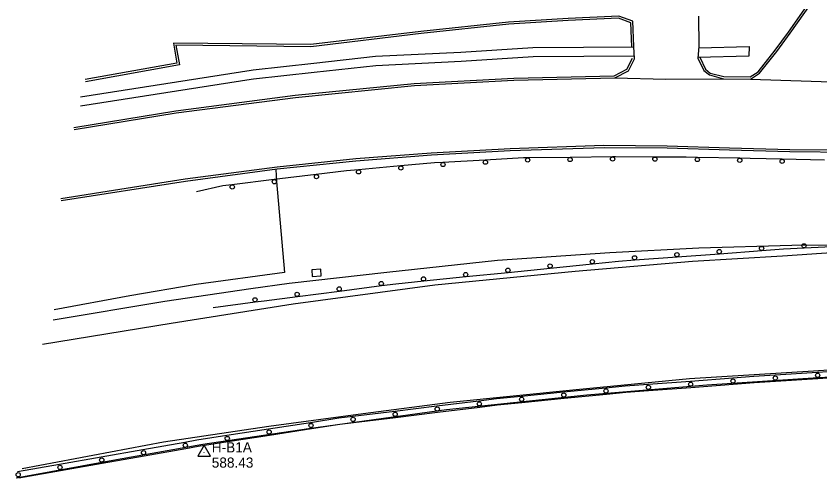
# Model space of a CAD drawing. Extents: x 2402803 to 2427059, y 6985292 to 6997652.
# Drawn here: x 2403515.4 to 2403894.2, y 6991813.9 to 6992031.6 of the extents above; entities that cross this region are included whole.
import ezdxf

# ---------------------------------------------------------------- set-up
doc = ezdxf.new("R2010")
doc.units = 0
for name, color, linetype in [('p_control ground ctrl', 7, 'Continuous'), ('p_drainage riprap', 7, 'Continuous'), ('p_dtm sidewalk', 7, 'Continuous'), ('p_road - paved curb', 7, 'Continuous'), ('p_road bridge end', 7, 'Continuous'), ('p_road conc barrier', 7, 'Continuous'), ('p_road guard rails', 7, 'Continuous'), ('V7 LEVEL 31', 7, 'Continuous')]:
    doc.layers.add(name, color=color, linetype=linetype)

msp = doc.modelspace()

# ---------------------------------------------------------------- linework, layer by layer
at = {"layer": 'p_control ground ctrl'}
for p, q in [((2403604.07, 6991829.43), (2403601.07, 6991824.23)), ((2403607.07, 6991824.23), (2403604.07, 6991829.43)), ((2403604.07, 6991825.95), (2403604.07, 6991825.99)), ((2403601.07, 6991824.23), (2403607.07, 6991824.23))]:
    msp.add_line(p, q, dxfattribs=at)
at = {"layer": 'p_drainage riprap'}
for points in [[(2403637.78, 6991959.32), (2403638.11, 6991953.54), (2403641.89, 6991910.76), (2403600.24, 6991905.07), (2403569.01, 6991899.69), (2403533.3, 6991893.12)], [(2403532.95, 6991888.46), (2403585.58, 6991897.26), (2403626.03, 6991903.26), (2403644.18, 6991905.72), (2403690.09, 6991910.93), (2403742.27, 6991916.53), (2403795.17, 6991920.18), (2403837.2, 6991922.33), (2403880.97, 6991923.55), (2403939.46, 6991923.79)]]:
    msp.add_lwpolyline(points, dxfattribs=at)
at = {"layer": 'p_dtm sidewalk'}
for points in [[(2403806.67, 6992016.94), (2403758.91, 6992016.61), (2403725.03, 6992014.37), (2403684.87, 6992012.47), (2403655.8, 6992009.27), (2403627.13, 6992006.13), (2403626.15, 6992005.91), (2403545.73, 6991993.37)], [(2403837.19, 6992016.66), (2403860.92, 6992017.16), (2403860.8, 6992012.64), (2403836.76, 6992012.09)], [(2403806.79, 6992012.66), (2403759.03, 6992012.33), (2403725.15, 6992010.09), (2403684.99, 6992008.19), (2403655.92, 6992004.99), (2403627.25, 6992001.85), (2403626.27, 6992001.63), (2403545.85, 6991989.09)]]:
    msp.add_lwpolyline(points, dxfattribs=at)
at = {"layer": 'p_road - paved curb'}
for points in [[(2403873.14, 6992015.43), (2403879.35, 6992024.04), (2403892.29, 6992042.47), (2403893.33, 6992046.18)], [(2403873.95, 6992014.85), (2403880.16, 6992023.46), (2403893.21, 6992042.04), (2403894.29, 6992045.91)], [(2403806.6, 6992017.25), (2403806.09, 6992029.16), (2403799.41, 6992031.54), (2403775.54, 6992030.46), (2403747.49, 6992028.7), (2403706.23, 6992024.32), (2403654.28, 6992018.13), (2403589.53, 6992018.84), (2403591.2, 6992009.33), (2403548.02, 6992001.63)], [(2403805.6, 6992017.21), (2403805.12, 6992028.44), (2403799.26, 6992030.53), (2403775.59, 6992029.46), (2403747.57, 6992027.7), (2403706.34, 6992023.33), (2403654.33, 6992017.13), (2403590.72, 6992017.83), (2403592.36, 6992008.52), (2403548.2, 6992000.65)], [(2403837.08, 6992031.56), (2403837.24, 6992017.22), (2403836.73, 6992011.71)], [(2403806.84, 6992011.34), (2403806.6, 6992017.25)], [(2403836.73, 6992011.71), (2403839.47, 6992005.94), (2403842.12, 6992003.81), (2403848.78, 6992002.07), (2403861.58, 6992001.89), (2403865.79, 6992004.6), (2403873.95, 6992014.85)], [(2403837.63, 6992012.14), (2403840.28, 6992006.58), (2403842.58, 6992004.72), (2403848.92, 6992003.07), (2403861.29, 6992002.89), (2403865.11, 6992005.35), (2403873.17, 6992015.47)], [(2403542.69, 6991979.06), (2403590.72, 6991986.9), (2403646.97, 6991994.25), (2403703.09, 6991999.87), (2403749.98, 6992002.37), (2403797.34, 6992003.38), (2403803.27, 6992006.5), (2403805.95, 6992011.79)], [(2403542.85, 6991978.07), (2403590.87, 6991985.91), (2403647.08, 6991993.26), (2403703.17, 6991998.87), (2403750.02, 6992001.37), (2403797.6, 6992002.39), (2403804.02, 6992005.76), (2403806.84, 6992011.34)], [(2403797.57, 6992002.5), (2403821.69, 6992001.76), (2403848.78, 6992002.07)], [(2403861.56, 6992001.89), (2403904.44, 6992000.5)], [(2403936.44, 6991968.29), (2403908.86, 6991968.31), (2403880, 6991968.6), (2403851.7, 6991969.36), (2403822.22, 6991970.3), (2403792.48, 6991970.5), (2403748.26, 6991969.01), (2403711.1, 6991966.96), (2403675.52, 6991964.25), (2403638.41, 6991960.41), (2403595.15, 6991954.64), (2403536.57, 6991945.44)], [(2403936.44, 6991967.29), (2403908.85, 6991967.31), (2403879.98, 6991967.6), (2403851.67, 6991968.36), (2403822.2, 6991969.3), (2403792.49, 6991969.5), (2403748.3, 6991968.01), (2403711.17, 6991965.96), (2403675.61, 6991963.25), (2403638.53, 6991959.42), (2403595.29, 6991953.65), (2403536.73, 6991944.45)], [(2403527.89, 6991876.98), (2403588.45, 6991886.88), (2403645.93, 6991895.97), (2403712.77, 6991904.89), (2403778.83, 6991911.37), (2403834.22, 6991916.11), (2403876.59, 6991918.51), (2403927.12, 6991921.97), (2403942.02, 6991922.78)], [(2403939.09, 6991867.4), (2403891.26, 6991864.17), (2403832.8, 6991860.58), (2403779.29, 6991855.47), (2403719.94, 6991849.45), (2403678.99, 6991844.06), (2403634.61, 6991838.18), (2403584.87, 6991830.81), (2403518.35, 6991818.19)], [(2403515.51, 6991814.01), (2403562.7, 6991822.61), (2403603.5, 6991829.83), (2403653.28, 6991837.15), (2403718.31, 6991846.1), (2403784.34, 6991853.15), (2403840.98, 6991857.79), (2403893.48, 6991861.21), (2403940.14, 6991863.6)]]:
    msp.add_lwpolyline(points, dxfattribs=at)
at = {"layer": 'p_road bridge end'}
msp.add_lwpolyline([(2403654.95, 6991908.81), (2403659.19, 6991909.13), (2403658.96, 6991912.28), (2403654.72, 6991911.96)], close=True, dxfattribs=at)
at = {"layer": 'p_road conc barrier'}
for p, q in [((2403873.13, 6991862.49), (2403893.08, 6991863.81)), ((2403813.28, 6991858.12), (2403833.22, 6991859.6)), ((2403833.22, 6991859.6), (2403853.16, 6991861.08)), ((2403873.33, 6991859.49), (2403893.28, 6991860.82)), ((2403773.41, 6991854.46), (2403793.3, 6991856.42)), ((2403813.51, 6991855.13), (2403833.44, 6991856.61)), ((2403833.44, 6991856.61), (2403853.38, 6991858.09)), ((2403753.51, 6991852.5), (2403773.41, 6991854.46)), ((2403753.81, 6991849.51), (2403773.7, 6991851.47)), ((2403773.7, 6991851.47), (2403793.59, 6991853.43)), ((2403693.88, 6991845.44), (2403713.73, 6991847.88)), ((2403713.73, 6991847.88), (2403733.57, 6991850.33)), ((2403714.09, 6991844.91), (2403733.94, 6991847.35)), ((2403674.04, 6991842.99), (2403693.88, 6991845.44)), ((2403694.25, 6991842.46), (2403714.09, 6991844.91)), ((2403634.44, 6991837.06), (2403654.18, 6991840.12)), ((2403674.41, 6991840.01), (2403694.25, 6991842.46)), ((2403614.71, 6991834), (2403634.44, 6991837.06)), ((2403634.9, 6991834.09), (2403654.64, 6991837.15)), ((2403615.17, 6991831.03), (2403634.9, 6991834.09)), ((2403575.23, 6991827.33), (2403594.92, 6991830.81)), ((2403555.54, 6991823.85), (2403575.23, 6991827.33)), ((2403575.76, 6991824.37), (2403595.45, 6991827.85)), ((2403535.85, 6991820.37), (2403555.54, 6991823.85)), ((2403536.37, 6991817.41), (2403556.06, 6991820.89)), ((2403556.06, 6991820.89), (2403575.76, 6991824.37)), ((2403516.16, 6991816.89), (2403535.85, 6991820.37)), ((2403516.68, 6991813.93), (2403536.37, 6991817.41))]:
    msp.add_line(p, q, dxfattribs=at)
for points in [[(2403853.16, 6991861.08), (2403863.04, 6991861.82), (2403873.13, 6991862.49)], [(2403893.08, 6991863.81), (2403902.86, 6991864.46), (2403913.12, 6991864.89)], [(2403853.38, 6991858.09), (2403863.25, 6991858.82), (2403873.33, 6991859.49)], [(2403893.28, 6991860.82), (2403903.03, 6991861.46), (2403913.25, 6991861.89)], [(2403793.3, 6991856.42), (2403802.53, 6991857.32), (2403813.28, 6991858.12)], [(2403793.59, 6991853.43), (2403802.79, 6991854.34), (2403813.51, 6991855.13)], [(2403733.57, 6991850.33), (2403741.79, 6991851.34), (2403753.51, 6991852.5)], [(2403733.94, 6991847.35), (2403742.12, 6991848.36), (2403753.81, 6991849.51)], [(2403654.18, 6991840.12), (2403667.58, 6991842.2), (2403674.04, 6991842.99)], [(2403654.64, 6991837.15), (2403668, 6991839.22), (2403674.41, 6991840.01)], [(2403594.92, 6991830.81), (2403600.67, 6991831.82), (2403614.71, 6991834)], [(2403595.45, 6991827.85), (2403601.16, 6991828.86), (2403615.17, 6991831.03)]]:
    msp.add_lwpolyline(points, dxfattribs=at)
for centre in [(2403893.18, 6991862.31), (2403833.33, 6991858.11), (2403853.27, 6991859.59), (2403873.23, 6991860.99), (2403793.44, 6991854.92), (2403813.4, 6991856.63), (2403753.66, 6991851), (2403773.55, 6991852.96), (2403713.91, 6991846.39), (2403733.75, 6991848.84), (2403694.07, 6991843.95), (2403674.22, 6991841.5), (2403634.67, 6991835.58), (2403654.41, 6991838.64), (2403614.94, 6991832.52), (2403595.18, 6991829.33), (2403575.49, 6991825.85), (2403555.8, 6991822.37), (2403536.11, 6991818.89), (2403516.42, 6991815.41)]:
    msp.add_circle(centre, 1, dxfattribs=at)
at = {"layer": 'p_road guard rails'}
for p, q in [((2403776.5, 6991964.97), (2403756.51, 6991964.73)), ((2403796.5, 6991965.21), (2403776.5, 6991964.97)), ((2403856.48, 6991964.58), (2403836.49, 6991964.97)), ((2403696.65, 6991960.95), (2403676.73, 6991959.15)), ((2403736.54, 6991963.72), (2403716.57, 6991962.62)), ((2403896.45, 6991963.61), (2403876.47, 6991964.11)), ((2403637.01, 6991954.48), (2403617.15, 6991952.05)), ((2403656.86, 6991956.9), (2403637.01, 6991954.48)), ((2403886.76, 6991922.3), (2403906.7, 6991923.32)), ((2403826.93, 6991918.12), (2403846.87, 6991919.59)), ((2403846.87, 6991919.59), (2403866.82, 6991921.06)), ((2403806.98, 6991916.65), (2403826.93, 6991918.12)), ((2403747.29, 6991910.79), (2403767.18, 6991912.81)), ((2403767.18, 6991912.81), (2403787.07, 6991914.84)), ((2403707.52, 6991906.75), (2403727.41, 6991908.77)), ((2403727.41, 6991908.77), (2403747.29, 6991910.79)), ((2403667.82, 6991902), (2403687.65, 6991904.55)), ((2403647.99, 6991899.45), (2403667.82, 6991902)), ((2403608.35, 6991894.18), (2403628.17, 6991896.88))]:
    msp.add_line(p, q, dxfattribs=at)
for points in [[(2403756.51, 6991964.73), (2403754.55, 6991964.71), (2403736.54, 6991963.72)], [(2403816.5, 6991965.14), (2403797.83, 6991965.23), (2403796.5, 6991965.21)], [(2403836.49, 6991964.97), (2403831.24, 6991965.07), (2403816.5, 6991965.14)], [(2403716.57, 6991962.62), (2403712.66, 6991962.4), (2403696.65, 6991960.95)], [(2403876.47, 6991964.11), (2403861.43, 6991964.48), (2403856.48, 6991964.58)], [(2403676.73, 6991959.15), (2403671.2, 6991958.65), (2403656.86, 6991956.9)], [(2403617.15, 6991952.05), (2403612.78, 6991951.52), (2403600.41, 6991948.82)], [(2403866.82, 6991921.06), (2403877.05, 6991921.81), (2403886.76, 6991922.3)], [(2403787.07, 6991914.84), (2403799.39, 6991916.09), (2403806.98, 6991916.65)], [(2403687.65, 6991904.55), (2403694.37, 6991905.41), (2403707.52, 6991906.75)], [(2403628.17, 6991896.88), (2403632.39, 6991897.45), (2403647.99, 6991899.45)]]:
    msp.add_lwpolyline(points, dxfattribs=at)
for centre in [(2403756.52, 6991963.73), (2403776.51, 6991963.97), (2403796.51, 6991964.21), (2403816.49, 6991964.14), (2403836.47, 6991963.97), (2403696.74, 6991959.96), (2403716.63, 6991961.62), (2403736.59, 6991962.72), (2403856.46, 6991963.58), (2403876.44, 6991963.11), (2403676.82, 6991958.15), (2403637.13, 6991953.48), (2403656.98, 6991955.91), (2403617.28, 6991951.06), (2403866.74, 6991922.05), (2403886.71, 6991923.3), (2403826.85, 6991919.12), (2403846.8, 6991920.58), (2403786.97, 6991915.83), (2403806.91, 6991917.65), (2403747.19, 6991911.79), (2403767.08, 6991913.81), (2403707.42, 6991907.74), (2403727.3, 6991909.76), (2403687.52, 6991905.54), (2403647.87, 6991900.45), (2403667.69, 6991902.99), (2403628.03, 6991897.87)]:
    msp.add_circle(centre, 1, dxfattribs=at)

# ---------------------------------------------------------------- texts
at = {"layer": 'p_control ground ctrl'}
msp.add_text('  H-B1A', height=4.8, dxfattribs=at).set_placement((2403604.07, 6991825.95))
at = {"layer": 'V7 LEVEL 31'}
msp.add_text('  588.43', height=4.8, dxfattribs=at).set_placement((2403604.07, 6991818.75))

doc.saveas('drawing.dxf')
